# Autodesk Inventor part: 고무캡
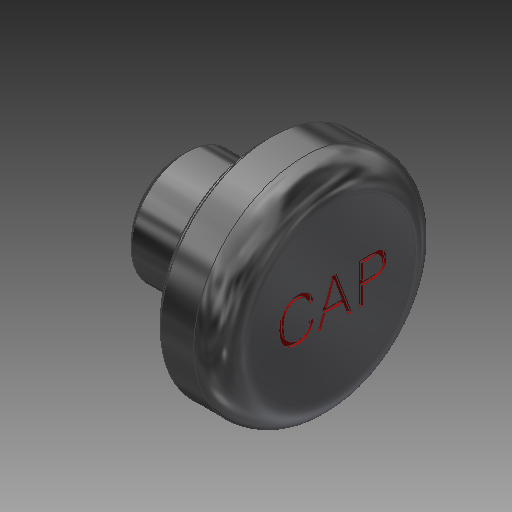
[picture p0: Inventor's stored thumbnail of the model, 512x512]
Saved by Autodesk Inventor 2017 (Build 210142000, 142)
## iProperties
Created: 2017-06
Part Number: 고무캡
Material: 고무
Document SubType Name: Modeling
Designer: mduedu
Density: 1 g/cm^3
Appearance: 고무 - 검은색 - 버전 1.1
Author: mduedu
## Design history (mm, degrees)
sketch "스케치1"
  geometry: L1 (0, 0)-(11, 0); L2 (11, 0)-(11, 8); L3 (11, 8)-(6.5, 8); L4 (0, 4)-(0, 0); L5 (0, 4)-(6, 4); L6 (6, 4)-(6, 7.5); L7 (6, 7.5)-(6.5, 7.5); L8 (6.5, 7.5)-(6.5, 8)
  constraints: 16 end point, 2 horizontal, 2 parallel, 2 perpendicular, 2 point on line, 1 vertical
  dimensions: "d0" = 16 diameter of L3 L1; "d2" = 8 diameter of L5 L1; "d6" = 5 distance between parallel lines of L2 L6; "d7" = 0.5 distance between parallel lines of L8 L6; "d8" = 15 diameter of L7 L1; "d9" = 6 distance between parallel lines of L6 L4
revolve "회전1" sketch "스케치1" stored, may be unused: angle "d10" = 90 deg
hole "구멍1" diameter "d22" = 5; stored, may be unused: countersink angle "d26" = 90 deg, drill point angle "d28" = 0 deg; dims "d23" = 6, "d24" = 4, "d25" = 2, "d27" = 6, "d30" = 10, "d31" = 10
chamfer "모따기1" distance "d13" = 0.5; stored, may be unused: second distance "d14" = 2, angle "d15" = 45 deg
fillet "모깎기3" dims "d29" = 1
fillet "모깎기1" dims "d16" = 0.1
fillet "모깎기2" dims "d17" = 2
sketch "스케치3"
  geometry: 2 further points
  constraints: 1 coincident, 1 other
feature "엠보싱1" sketch "스케치3" dims "d18" = 0.2, "d19" = 0
node "솔리드1"
